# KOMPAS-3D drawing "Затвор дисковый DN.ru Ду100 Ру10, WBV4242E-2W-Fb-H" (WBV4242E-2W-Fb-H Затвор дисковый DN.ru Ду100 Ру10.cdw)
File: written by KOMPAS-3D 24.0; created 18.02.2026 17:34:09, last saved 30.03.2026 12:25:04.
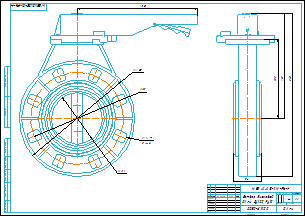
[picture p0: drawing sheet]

Document properties: Автор: R2D2; Форматы листов документа: A2; Полное имя файла: WBV4242E-2W-Fb-H Затвор дисковый DN.ru Ду100 Ру10.m3d; Масса: 2.44; Наименование: Затвор дисковый DN.ru Ду100 Ру10; Количество листов документа: 1; Примечание: D050-81200

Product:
- Component [assembly]: Сборка1  | qty 1  | Автор: R2D2; source file: исходные материалы\dn100_3d_step.a3d
- Part/product: Затвор дисковый DN.ru Ду100 Ру10  | designation WBV4242E-2W-Fb-H
    Масса: 2.44
    Раздел спецификации: Прочие изделия
    Примечание: D050-81200

Views: Вид 1, Сзади
Referenced files in E:\Работа\Зайцев\WBV4242E-2W-Fb-ISO Затвор дисковый DN.ru Ду50-200 Ру10\DN100\: WBV4242E-2W-Fb-ISO Затвор дисковый DN.ru Ду100 Ру10.m3d
Referenced files in E:\Работа\Зайцев\WBV4242E-2W-Fb-H Затвор дисковый DN.ru Ду50-200 Ру10\DN100\: WBV4242E-2W-Fb-H Затвор дисковый DN.ru Ду100 Ру10.m3d
Referenced files in E:\Работа\Зайцев\Для компаса\: чертеж DN.ru А3.cdt
Referenced files in E:\Работа\Зайцев\WBV4242E-2W-Fb-H Затвор дисковый DN.ru Ду50-200 Ру10\DN100\исходные материалы\: Деталь1 Деталь1.m3d, Деталь2 Деталь2.m3d, dn100_3d_step.a3d
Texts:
  WBV4242E-2W-Fb-H
  чертеж DN.ru А3.cdt
  Затвор дисковый
  DN.ru Ду100 Ру10
  Твердое тело1
  Деталь1
  Деталь1 Деталь1
  Деталь2
  Деталь2 Деталь2
  Сборка1
  Сборка1 Сборка1
  Затвор дисковый DN.ru Ду100 Ру10
  WBV4242E-2W-Fb-H Затвор дисковый DN.ru Ду100 Ру10
Dimensions and other numbers on the sheet: 0; 3; 2; 4; 226,5; 100; 181; 8 отв.; 236; 1:1; 1; 2,44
